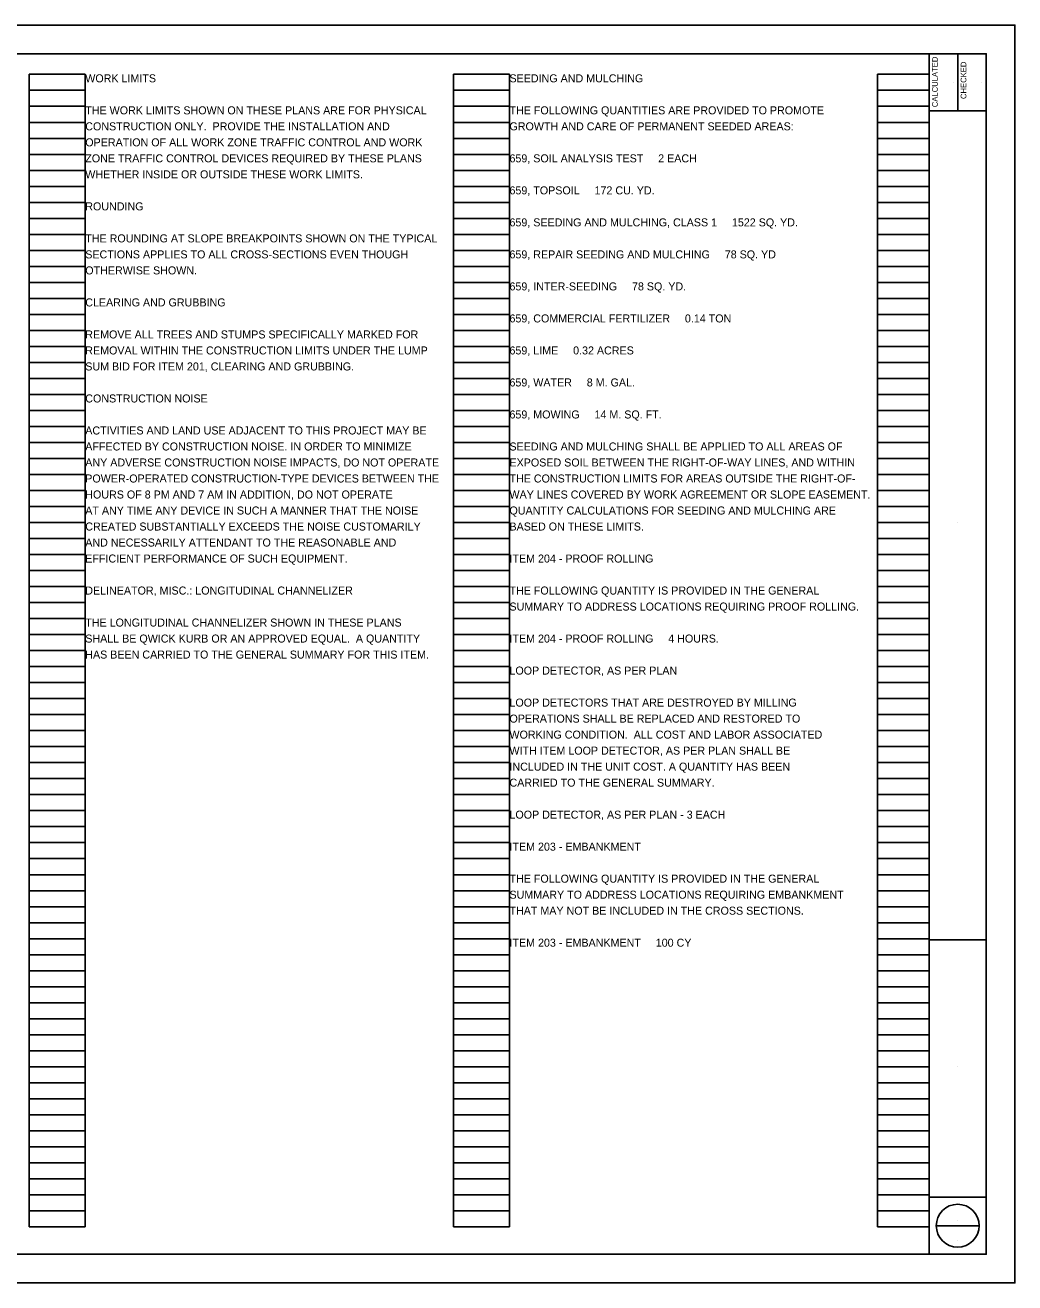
# Model space of a CAD drawing. Extents: x 0 to 58.9, y -9.9 to 22.
# Drawn here: x 16.69 to 34, y 0 to 22 of the extents above; entities that cross this region are included whole.
import ezdxf

# ---------------------------------------------------------------- set-up
doc = ezdxf.new("R2010")
doc.units = 0
for name, color, linetype in [('SH_Border', 7, 'Continuous'), ('SH_Cut_Line', 7, 'Continuous'), ('SH_Data', 7, 'Continuous'), ('SH_Text', 7, 'Continuous')]:
    doc.layers.add(name, color=color, linetype=linetype)

msp = doc.modelspace()

# ---------------------------------------------------------------- linework, layer by layer
at = {"layer": 'SH_Border'}
for p, q in [((32.5, 0.5), (32.5, 21.5)), ((33, 21.5), (33, 20.5)), ((32.5, 20.5), (33.5, 20.5)), ((32.5, 6), (33.5, 6)), ((32.5, 1.5), (33.5, 1.5))]:
    msp.add_line(p, q, dxfattribs=at)
msp.add_lwpolyline([(2, 21.5), (33.5, 21.5), (33.5, 0.5), (2, 0.5)], close=True, dxfattribs=at)
at = {"layer": 'SH_Cut_Line'}
msp.add_lwpolyline([(0, 0), (34, 0), (34, 22), (0, 22)], close=True, dxfattribs=at)
at = {"layer": 'SH_Data'}
for p, q in [((16.76, 0.98), (16.76, 21.14)), ((16.76, 21.14), (17.74, 21.14)), ((17.74, 0.98), (17.74, 21.14)), ((24.18, 0.98), (24.18, 21.14)), ((24.18, 21.14), (25.16, 21.14)), ((25.16, 0.98), (25.16, 21.14)), ((31.6, 0.98), (31.6, 21.14)), ((31.6, 21.14), (32.5, 21.14)), ((32.5, 0.98), (32.5, 21.14)), ((32.92, 21.004), (32.92, 21.004)), ((33.42, 21.004), (33.42, 21.004)), ((16.76, 20.86), (17.74, 20.86)), ((24.18, 20.86), (25.16, 20.86)), ((31.6, 20.86), (32.5, 20.86)), ((16.76, 20.58), (17.74, 20.58)), ((24.18, 20.58), (25.16, 20.58)), ((31.6, 20.58), (32.5, 20.58)), ((16.76, 20.3), (17.74, 20.3)), ((24.18, 20.3), (25.16, 20.3)), ((31.6, 20.3), (32.5, 20.3)), ((16.76, 20.02), (17.74, 20.02)), ((24.18, 20.02), (25.16, 20.02)), ((31.6, 20.02), (32.5, 20.02)), ((16.76, 19.74), (17.74, 19.74)), ((24.18, 19.74), (25.16, 19.74)), ((31.6, 19.74), (32.5, 19.74)), ((16.76, 19.46), (17.74, 19.46)), ((24.18, 19.46), (25.16, 19.46)), ((31.6, 19.46), (32.5, 19.46)), ((16.76, 19.18), (17.74, 19.18)), ((24.18, 19.18), (25.16, 19.18)), ((31.6, 19.18), (32.5, 19.18)), ((16.76, 18.9), (17.74, 18.9)), ((24.18, 18.9), (25.16, 18.9)), ((31.6, 18.9), (32.5, 18.9)), ((16.76, 18.62), (17.74, 18.62)), ((24.18, 18.62), (25.16, 18.62)), ((31.6, 18.62), (32.5, 18.62)), ((16.76, 18.34), (17.74, 18.34)), ((24.18, 18.34), (25.16, 18.34)), ((31.6, 18.34), (32.5, 18.34)), ((16.76, 18.06), (17.74, 18.06)), ((24.18, 18.06), (25.16, 18.06)), ((31.6, 18.06), (32.5, 18.06)), ((16.76, 17.78), (17.74, 17.78)), ((24.18, 17.78), (25.16, 17.78)), ((31.6, 17.78), (32.5, 17.78)), ((16.76, 17.5), (17.74, 17.5)), ((24.18, 17.5), (25.16, 17.5)), ((31.6, 17.5), (32.5, 17.5)), ((16.76, 17.22), (17.74, 17.22)), ((24.18, 17.22), (25.16, 17.22)), ((31.6, 17.22), (32.5, 17.22)), ((16.76, 16.94), (17.74, 16.94)), ((24.18, 16.94), (25.16, 16.94)), ((31.6, 16.94), (32.5, 16.94)), ((16.76, 16.66), (17.74, 16.66)), ((24.18, 16.66), (25.16, 16.66)), ((31.6, 16.66), (32.5, 16.66)), ((16.76, 16.38), (17.74, 16.38)), ((24.18, 16.38), (25.16, 16.38)), ((31.6, 16.38), (32.5, 16.38)), ((16.76, 16.1), (17.74, 16.1)), ((24.18, 16.1), (25.16, 16.1)), ((31.6, 16.1), (32.5, 16.1)), ((16.76, 15.82), (17.74, 15.82)), ((24.18, 15.82), (25.16, 15.82)), ((31.6, 15.82), (32.5, 15.82)), ((16.76, 15.54), (17.74, 15.54)), ((24.18, 15.54), (25.16, 15.54)), ((31.6, 15.54), (32.5, 15.54)), ((16.76, 15.26), (17.74, 15.26)), ((24.18, 15.26), (25.16, 15.26)), ((31.6, 15.26), (32.5, 15.26)), ((16.76, 14.98), (17.74, 14.98)), ((24.18, 14.98), (25.16, 14.98)), ((31.6, 14.98), (32.5, 14.98)), ((16.76, 14.7), (17.74, 14.7)), ((24.18, 14.7), (25.16, 14.7)), ((31.6, 14.7), (32.5, 14.7)), ((16.76, 14.42), (17.74, 14.42)), ((24.18, 14.42), (25.16, 14.42)), ((31.6, 14.42), (32.5, 14.42)), ((16.76, 14.14), (17.74, 14.14)), ((24.18, 14.14), (25.16, 14.14)), ((31.6, 14.14), (32.5, 14.14)), ((16.76, 13.86), (17.74, 13.86)), ((24.18, 13.86), (25.16, 13.86)), ((31.6, 13.86), (32.5, 13.86)), ((16.76, 13.58), (17.74, 13.58)), ((24.18, 13.58), (25.16, 13.58)), ((31.6, 13.58), (32.5, 13.58)), ((16.76, 13.3), (17.74, 13.3)), ((24.18, 13.3), (25.16, 13.3)), ((31.6, 13.3), (32.5, 13.3)), ((33, 13.292), (33, 13.292)), ((16.76, 13.02), (17.74, 13.02)), ((24.18, 13.02), (25.16, 13.02)), ((31.6, 13.02), (32.5, 13.02)), ((16.76, 12.74), (17.74, 12.74)), ((24.18, 12.74), (25.16, 12.74)), ((31.6, 12.74), (32.5, 12.74)), ((16.76, 12.46), (17.74, 12.46)), ((24.18, 12.46), (25.16, 12.46)), ((31.6, 12.46), (32.5, 12.46)), ((16.76, 12.18), (17.74, 12.18)), ((24.18, 12.18), (25.16, 12.18)), ((31.6, 12.18), (32.5, 12.18)), ((16.76, 11.9), (17.74, 11.9)), ((24.18, 11.9), (25.16, 11.9)), ((31.6, 11.9), (32.5, 11.9)), ((16.76, 11.62), (17.74, 11.62)), ((24.18, 11.62), (25.16, 11.62)), ((31.6, 11.62), (32.5, 11.62)), ((16.76, 11.34), (17.74, 11.34)), ((24.18, 11.34), (25.16, 11.34)), ((31.6, 11.34), (32.5, 11.34)), ((16.76, 11.06), (17.74, 11.06)), ((24.18, 11.06), (25.16, 11.06)), ((31.6, 11.06), (32.5, 11.06)), ((16.76, 10.78), (17.74, 10.78)), ((24.18, 10.78), (25.16, 10.78)), ((31.6, 10.78), (32.5, 10.78)), ((16.76, 10.5), (17.74, 10.5)), ((24.18, 10.5), (25.16, 10.5)), ((31.6, 10.5), (32.5, 10.5)), ((16.76, 10.22), (17.74, 10.22)), ((24.18, 10.22), (25.16, 10.22)), ((31.6, 10.22), (32.5, 10.22)), ((16.76, 9.94), (17.74, 9.94)), ((24.18, 9.94), (25.16, 9.94)), ((31.6, 9.94), (32.5, 9.94)), ((16.76, 9.66), (17.74, 9.66)), ((24.18, 9.66), (25.16, 9.66)), ((31.6, 9.66), (32.5, 9.66)), ((16.76, 9.38), (17.74, 9.38)), ((24.18, 9.38), (25.16, 9.38)), ((31.6, 9.38), (32.5, 9.38)), ((16.76, 9.1), (17.74, 9.1)), ((24.18, 9.1), (25.16, 9.1)), ((31.6, 9.1), (32.5, 9.1)), ((16.76, 8.82), (17.74, 8.82)), ((24.18, 8.82), (25.16, 8.82)), ((31.6, 8.82), (32.5, 8.82)), ((16.76, 8.54), (17.74, 8.54)), ((24.18, 8.54), (25.16, 8.54)), ((31.6, 8.54), (32.5, 8.54)), ((16.76, 8.26), (17.74, 8.26)), ((24.18, 8.26), (25.16, 8.26)), ((31.6, 8.26), (32.5, 8.26)), ((16.76, 7.98), (17.74, 7.98)), ((24.18, 7.98), (25.16, 7.98)), ((31.6, 7.98), (32.5, 7.98)), ((16.76, 7.7), (17.74, 7.7)), ((24.18, 7.7), (25.16, 7.7)), ((31.6, 7.7), (32.5, 7.7)), ((16.76, 7.42), (17.74, 7.42)), ((24.18, 7.42), (25.16, 7.42)), ((31.6, 7.42), (32.5, 7.42)), ((16.76, 7.14), (17.74, 7.14)), ((24.18, 7.14), (25.16, 7.14)), ((31.6, 7.14), (32.5, 7.14)), ((16.76, 6.86), (17.74, 6.86)), ((24.18, 6.86), (25.16, 6.86)), ((31.6, 6.86), (32.5, 6.86)), ((16.76, 6.58), (17.74, 6.58)), ((24.18, 6.58), (25.16, 6.58)), ((31.6, 6.58), (32.5, 6.58)), ((16.76, 6.3), (17.74, 6.3)), ((24.18, 6.3), (25.16, 6.3)), ((31.6, 6.3), (32.5, 6.3)), ((16.76, 6.02), (17.74, 6.02)), ((24.18, 6.02), (25.16, 6.02)), ((31.6, 6.02), (32.5, 6.02)), ((16.76, 5.74), (17.74, 5.74)), ((24.18, 5.74), (25.16, 5.74)), ((31.6, 5.74), (32.5, 5.74)), ((16.76, 5.46), (17.74, 5.46)), ((24.18, 5.46), (25.16, 5.46)), ((31.6, 5.46), (32.5, 5.46)), ((16.76, 5.18), (17.74, 5.18)), ((24.18, 5.18), (25.16, 5.18)), ((31.6, 5.18), (32.5, 5.18)), ((16.76, 4.9), (17.74, 4.9)), ((24.18, 4.9), (25.16, 4.9)), ((31.6, 4.9), (32.5, 4.9)), ((16.76, 4.62), (17.74, 4.62)), ((24.18, 4.62), (25.16, 4.62)), ((31.6, 4.62), (32.5, 4.62)), ((16.76, 4.34), (17.74, 4.34)), ((24.18, 4.34), (25.16, 4.34)), ((31.6, 4.34), (32.5, 4.34)), ((16.76, 4.06), (17.74, 4.06)), ((24.18, 4.06), (25.16, 4.06)), ((31.6, 4.06), (32.5, 4.06)), ((16.76, 3.78), (17.74, 3.78)), ((24.18, 3.78), (25.16, 3.78)), ((31.6, 3.78), (32.5, 3.78)), ((33, 3.792), (33, 3.792)), ((16.76, 3.5), (17.74, 3.5)), ((24.18, 3.5), (25.16, 3.5)), ((31.6, 3.5), (32.5, 3.5)), ((16.76, 3.22), (17.74, 3.22)), ((24.18, 3.22), (25.16, 3.22)), ((31.6, 3.22), (32.5, 3.22)), ((16.76, 2.94), (17.74, 2.94)), ((24.18, 2.94), (25.16, 2.94)), ((31.6, 2.94), (32.5, 2.94)), ((16.76, 2.66), (17.74, 2.66)), ((24.18, 2.66), (25.16, 2.66)), ((31.6, 2.66), (32.5, 2.66)), ((16.76, 2.38), (17.74, 2.38)), ((24.18, 2.38), (25.16, 2.38)), ((31.6, 2.38), (32.5, 2.38)), ((16.76, 2.1), (17.74, 2.1)), ((24.18, 2.1), (25.16, 2.1)), ((31.6, 2.1), (32.5, 2.1)), ((16.76, 1.82), (17.74, 1.82)), ((24.18, 1.82), (25.16, 1.82)), ((31.6, 1.82), (32.5, 1.82)), ((16.76, 1.54), (17.74, 1.54)), ((24.18, 1.54), (25.16, 1.54)), ((31.6, 1.54), (32.5, 1.54)), ((16.76, 1.26), (17.74, 1.26)), ((24.18, 1.26), (25.16, 1.26)), ((31.6, 1.26), (32.5, 1.26)), ((16.76, 0.98), (17.74, 0.98)), ((24.18, 0.98), (25.16, 0.98)), ((31.6, 0.98), (32.5, 0.98)), ((32.625, 1), (33.375, 1)), ((33, 1.085), (33, 1.085)), ((33, 0.745), (33, 0.745))]:
    msp.add_line(p, q, dxfattribs=at)
msp.add_circle((33, 1), 0.375, dxfattribs=at)

# ---------------------------------------------------------------- texts
for s, p in [('CALCULATED', (32.652, 20.565)), ('CHECKED', (33.152, 20.708))]:
    msp.add_text(s, height=0.1, rotation=90, dxfattribs=at).set_placement(p)
at = {"layer": 'SH_Text'}
for s, p in [('WORK LIMITS', (17.74, 21)), ('SEEDING AND MULCHING', (25.16, 21)), ('THE WORK LIMITS SHOWN ON THESE PLANS ARE FOR PHYSICAL', (17.74, 20.44)), ('THE FOLLOWING QUANTITIES ARE PROVIDED TO PROMOTE', (25.16, 20.44)), ('CONSTRUCTION ONLY.  PROVIDE THE INSTALLATION AND', (17.74, 20.16)), ('GROWTH AND CARE OF PERMANENT SEEDED AREAS:', (25.16, 20.16)), ('OPERATION OF ALL WORK ZONE TRAFFIC CONTROL AND WORK', (17.74, 19.88)), ('ZONE TRAFFIC CONTROL DEVICES REQUIRED BY THESE PLANS', (17.74, 19.6)), ('659, SOIL ANALYSIS TEST     2 EACH', (25.16, 19.6)), ('WHETHER INSIDE OR OUTSIDE THESE WORK LIMITS.', (17.74, 19.32)), ('659, TOPSOIL     172 CU. YD.', (25.16, 19.04)), ('ROUNDING', (17.74, 18.76)), ('659, SEEDING AND MULCHING, CLASS 1     1522 SQ. YD.', (25.16, 18.48)), ('THE ROUNDING AT SLOPE BREAKPOINTS SHOWN ON THE TYPICAL', (17.74, 18.2)), ('SECTIONS APPLIES TO ALL CROSS-SECTIONS EVEN THOUGH', (17.74, 17.92)), ('659, REPAIR SEEDING AND MULCHING     78 SQ. YD', (25.16, 17.92)), ('OTHERWISE SHOWN.', (17.74, 17.64)), ('659, INTER-SEEDING     78 SQ. YD.', (25.16, 17.36)), ('CLEARING AND GRUBBING', (17.74, 17.08)), ('659, COMMERCIAL FERTILIZER     0.14 TON', (25.16, 16.8)), ('REMOVE ALL TREES AND STUMPS SPECIFICALLY MARKED FOR', (17.74, 16.52)), ('REMOVAL WITHIN THE CONSTRUCTION LIMITS UNDER THE LUMP', (17.74, 16.24)), ('659, LIME     0.32 ACRES', (25.16, 16.24)), ('SUM BID FOR ITEM 201, CLEARING AND GRUBBING.', (17.74, 15.96)), ('659, WATER     8 M. GAL.', (25.16, 15.68)), ('CONSTRUCTION NOISE', (17.74, 15.4)), ('659, MOWING     14 M. SQ. FT.', (25.16, 15.12)), ('ACTIVITIES AND LAND USE ADJACENT TO THIS PROJECT MAY BE', (17.74, 14.84)), ('AFFECTED BY CONSTRUCTION NOISE. IN ORDER TO MINIMIZE', (17.74, 14.56)), ('SEEDING AND MULCHING SHALL BE APPLIED TO ALL AREAS OF', (25.16, 14.56)), ('ANY ADVERSE CONSTRUCTION NOISE IMPACTS, DO NOT OPERATE', (17.74, 14.28)), ('EXPOSED SOIL BETWEEN THE RIGHT-OF-WAY LINES, AND WITHIN', (25.16, 14.28)), ('POWER-OPERATED CONSTRUCTION-TYPE DEVICES BETWEEN THE', (17.74, 14)), ('THE CONSTRUCTION LIMITS FOR AREAS OUTSIDE THE RIGHT-OF-', (25.16, 14)), ('HOURS OF 8 PM AND 7 AM IN ADDITION, DO NOT OPERATE', (17.74, 13.72)), ('WAY LINES COVERED BY WORK AGREEMENT OR SLOPE EASEMENT.', (25.16, 13.72)), ('AT ANY TIME ANY DEVICE IN SUCH A MANNER THAT THE NOISE', (17.74, 13.44)), ('QUANTITY CALCULATIONS FOR SEEDING AND MULCHING ARE', (25.16, 13.44)), ('CREATED SUBSTANTIALLY EXCEEDS THE NOISE CUSTOMARILY', (17.74, 13.16)), ('BASED ON THESE LIMITS.', (25.16, 13.16)), ('AND NECESSARILY ATTENDANT TO THE REASONABLE AND', (17.74, 12.88)), ('EFFICIENT PERFORMANCE OF SUCH EQUIPMENT.', (17.74, 12.6)), ('ITEM 204 - PROOF ROLLING', (25.16, 12.6)), ('DELINEATOR, MISC.: LONGITUDINAL CHANNELIZER', (17.74, 12.04)), ('THE FOLLOWING QUANTITY IS PROVIDED IN THE GENERAL', (25.16, 12.04)), ('SUMMARY TO ADDRESS LOCATIONS REQUIRING PROOF ROLLING.', (25.16, 11.76)), ('THE LONGITUDINAL CHANNELIZER SHOWN IN THESE PLANS', (17.74, 11.48)), ('SHALL BE QWICK KURB OR AN APPROVED EQUAL.  A QUANTITY', (17.74, 11.2)), ('ITEM 204 - PROOF ROLLING     4 HOURS.', (25.16, 11.2)), ('HAS BEEN CARRIED TO THE GENERAL SUMMARY FOR THIS ITEM.', (17.74, 10.92)), ('LOOP DETECTOR, AS PER PLAN', (25.16, 10.64)), ('LOOP DETECTORS THAT ARE DESTROYED BY MILLING', (25.16, 10.08)), ('OPERATIONS SHALL BE REPLACED AND RESTORED TO', (25.16, 9.8)), ('WORKING CONDITION.  ALL COST AND LABOR ASSOCIATED', (25.16, 9.52)), ('WITH ITEM LOOP DETECTOR, AS PER PLAN SHALL BE', (25.16, 9.24)), ('INCLUDED IN THE UNIT COST. A QUANTITY HAS BEEN', (25.16, 8.96)), ('CARRIED TO THE GENERAL SUMMARY.', (25.16, 8.68)), ('LOOP DETECTOR, AS PER PLAN - 3 EACH', (25.16, 8.12)), ('ITEM 203 - EMBANKMENT', (25.16, 7.56)), ('THE FOLLOWING QUANTITY IS PROVIDED IN THE GENERAL', (25.16, 7)), ('SUMMARY TO ADDRESS LOCATIONS REQUIRING EMBANKMENT', (25.16, 6.72)), ('THAT MAY NOT BE INCLUDED IN THE CROSS SECTIONS.', (25.16, 6.44)), ('ITEM 203 - EMBANKMENT     100 CY', (25.16, 5.88))]:
    msp.add_text(s, height=0.14, dxfattribs=at).set_placement(p)

doc.saveas('drawing.dxf')
